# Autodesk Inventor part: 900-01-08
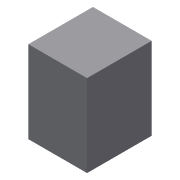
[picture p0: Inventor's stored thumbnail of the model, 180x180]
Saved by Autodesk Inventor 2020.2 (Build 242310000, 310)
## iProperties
Created: 2015-11
Part Number: 900-01-08
Material: Ogólny
Document SubType Name: Modeling
Designer: F.Stasiak
Density: 1 g/cm^3
Appearance: Domyślna
Catalog Web Link: www.expertbooks.pl
Manager: www.cadconsulting.pl
Company: Fabian Stasiak CAD Consulting
Author: F.Stasiak
Subject: Zbiór ćwiczeń. Autodesk Inventor 2020. Kurs Professional
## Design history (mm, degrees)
sketch "Szkic1"
  geometry: L1 (0, 0)-(50, 0); L2 (50, 0)-(50, 55); L3 (50, 55)-(0, 55); L4 (0, 55)-(0, 0)
  constraints: 8 end point, 2 parallel, 1 horizontal, 1 perpendicular
  dimensions: "d0" = 50 distance of L3.end L2.end; "d1" = 55 distance of L2.end L1.end
extrude "Wyciągnięcie proste1" new body sketch "Szkic1" distance "d2" = 70; taper "d3" = 0 deg
node "Bryła1"
